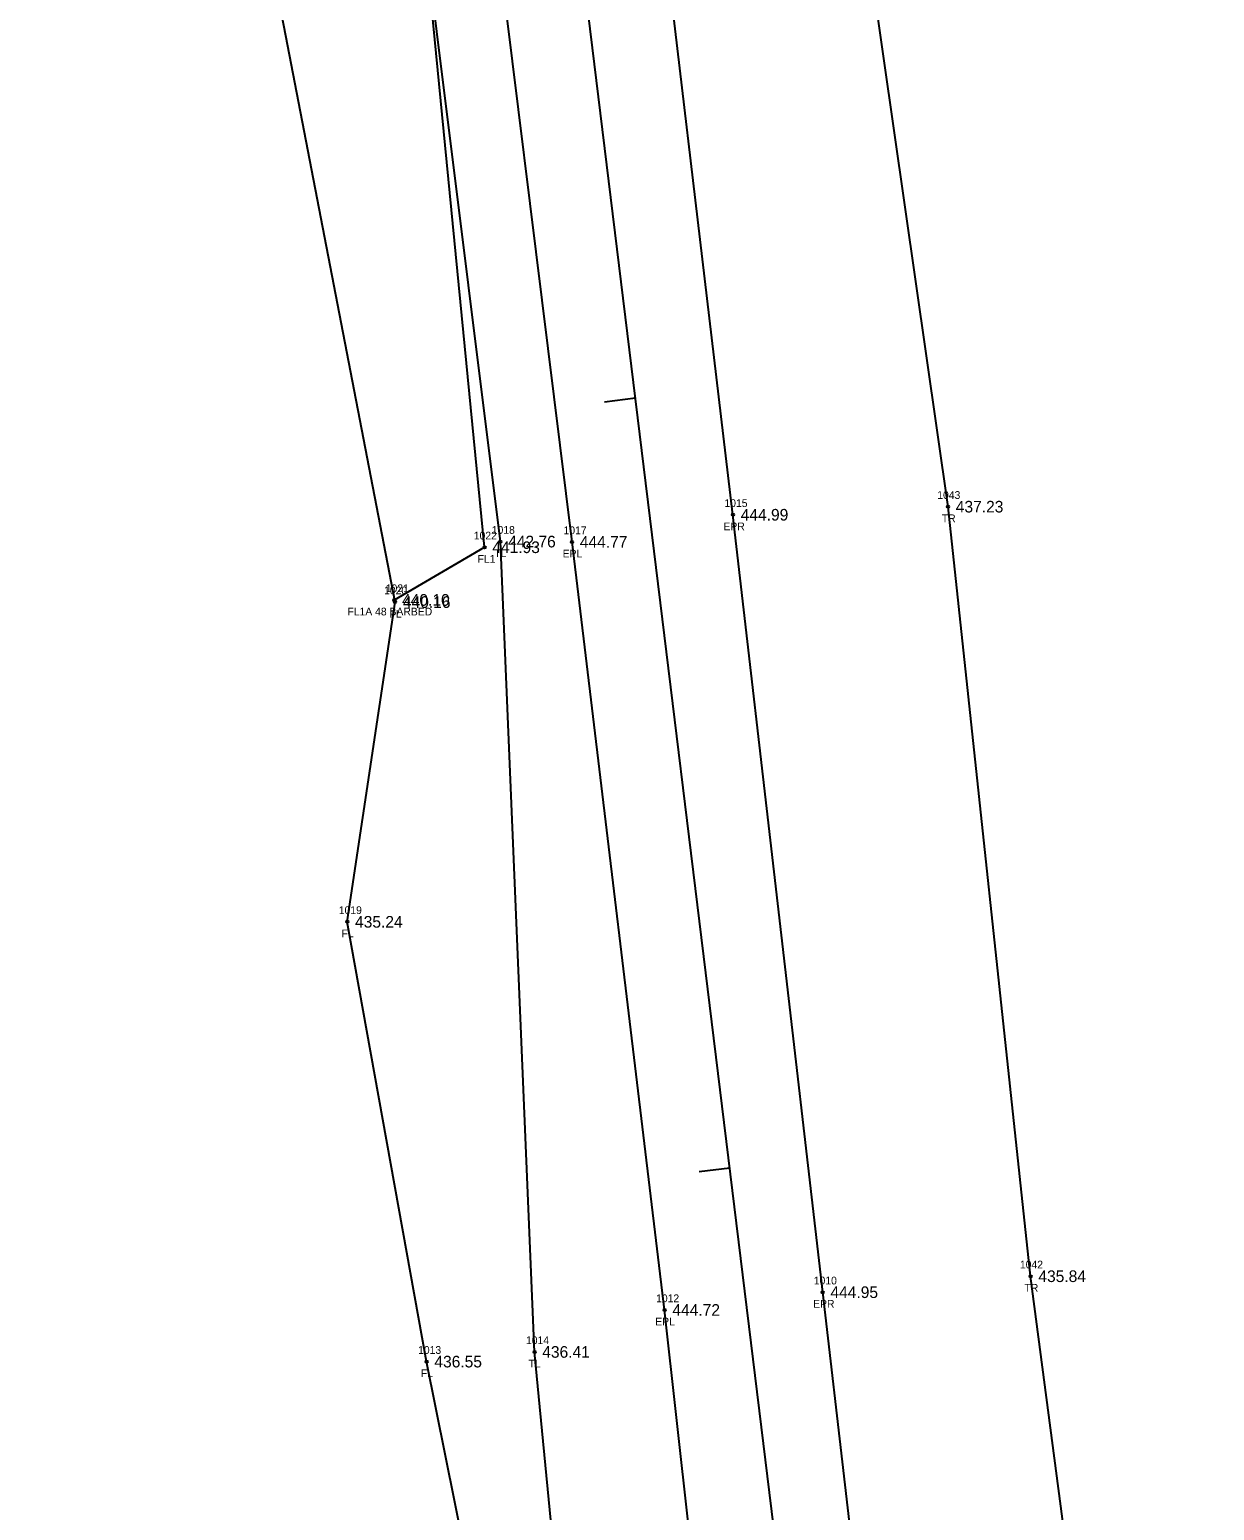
# Model space of a CAD drawing. Extents: x 1858454 to 1858924, y 1147053 to 1148170.
# Drawn here: x 1858633.8 to 1858786.6, y 1147243.8 to 1147434.7 of the extents above; entities that cross this region are included whole.
import ezdxf

# ---------------------------------------------------------------- set-up
doc = ezdxf.new("R2010")
doc.units = 0
for name, color, linetype in [('RD_EX_Fence_Other', 7, 'Continuous'), ('RD_EX_Fence_Other_txCode', 7, 'Continuous'), ('RD_EX_Road', 7, 'Continuous'), ('RD_EX_Road_txCode', 7, 'Continuous'), ('RD_EX_TX_Fence_Other_ELEV', 7, 'Continuous'), ('RD_EX_TX_Road_ELEV', 7, 'Continuous'), ('RD_EX_TX_VEG_ELEV', 7, 'Continuous'), ('RD_EX_VEG', 7, 'Continuous'), ('RD_EX_VEG_txCode', 7, 'Continuous'), ('RD_HC_Cl', 7, 'Continuous'), ('RD_HC_Data_Tic', 7, 'Continuous'), ('RD_SMD_Locator', 7, 'Continuous')]:
    doc.layers.add(name, color=color, linetype=linetype)

msp = doc.modelspace()

# ---------------------------------------------------------------- linework, layer by layer
at = {"layer": 'RD_EX_Fence_Other'}
for points in [[(1858680.85, 1147361.22), (1858692.48, 1147368.01), (1858682.77, 1147467.32), (1858662.27, 1147567.54), (1858637.61, 1147560.56)], [(1858724.59, 1147070.61), (1858704.63, 1147165.53), (1858685.01, 1147263.02), (1858674.78, 1147319.72), (1858680.95, 1147360.94), (1858660.16, 1147468.71), (1858637.61, 1147560.56)]]:
    msp.add_lwpolyline(points, dxfattribs=at)
at = {"layer": 'RD_EX_Road'}
for points in [[(1858739.58, 1147072.32), (1858726.74, 1147170.58), (1858715.7, 1147269.68), (1858703.76, 1147368.69), (1858691.45, 1147468.11), (1858680.5, 1147569.65), (1858689.32, 1147570.79)], [(1858760.33, 1147074.17), (1858747.61, 1147172.63), (1858736.08, 1147271.97), (1858724.51, 1147372.2), (1858712.86, 1147470.38), (1858700.06, 1147571.96), (1858689.32, 1147570.79)]]:
    msp.add_lwpolyline(points, dxfattribs=at)
at = {"layer": 'RD_EX_VEG'}
for points in [[(1858786.58, 1147073.62), (1858775.98, 1147174.64), (1858762.89, 1147274.03), (1858752.24, 1147373.24), (1858736.96, 1147479.89), (1858729.06, 1147571.9), (1858711.6, 1147670.3), (1858690.41, 1147764.38), (1858680.89, 1147862.43), (1858668.42, 1147961.01), (1858651.26, 1148061.01), (1858641.53, 1148160.37)], [(1858726.29, 1147071.02), (1858708.41, 1147166.41), (1858698.92, 1147264.27), (1858694.52, 1147368.74), (1858682.22, 1147467.57), (1858636.43, 1147636.58), (1858645.41, 1147757.54), (1858631.11, 1147856.08), (1858618.46, 1147956.68), (1858606.82, 1148055.62), (1858592.91, 1148154.69)]]:
    msp.add_lwpolyline(points, dxfattribs=at)
at = {"layer": 'RD_HC_Cl'}
msp.add_line((1858750.25, 1147074.55), (1858617.68, 1148156.23), dxfattribs=at)
at = {"layer": 'RD_HC_Data_Tic'}
for p, q in [((1858711.93, 1147387.21), (1858707.96, 1147386.73)), ((1858724.1, 1147287.96), (1858720.13, 1147287.47))]:
    msp.add_line(p, q, dxfattribs=at)
at = {"layer": 'RD_SMD_Locator'}
for centre in [(1858724.51, 1147372.2), (1858752.24, 1147373.24), (1858694.52, 1147368.74), (1858703.76, 1147368.69), (1858692.48, 1147368.01), (1858680.85, 1147361.22), (1858680.95, 1147360.94), (1858674.78, 1147319.72), (1858762.89, 1147274.03), (1858736.08, 1147271.97), (1858715.7, 1147269.68), (1858698.92, 1147264.27), (1858685.01, 1147263.02)]:
    msp.add_circle(centre, 0.15, dxfattribs=at)

# ---------------------------------------------------------------- texts
at = {"layer": 'RD_EX_Fence_Other_txCode'}
for s, p in [('1022', (1858691.09, 1147369.01)), ('FL1', (1858691.58, 1147366.01)), ('1020', (1858679.52, 1147361.94)), ('1021', (1858679.74, 1147362.22)), ('FL1A 48 BARBED', (1858674.8, 1147359.22)), ('FL', (1858680.22, 1147358.94)), ('1019', (1858673.68, 1147320.72)), ('FL', (1858674.05, 1147317.72)), ('1013', (1858683.91, 1147264.02)), ('FL', (1858684.28, 1147261.02))]:
    msp.add_text(s, height=1, dxfattribs=at).set_placement(p)
at = {"layer": 'RD_EX_Road_txCode'}
for s, p in [('1015', (1858723.41, 1147373.2)), ('1017', (1858702.66, 1147369.69)), ('EPR', (1858723.28, 1147370.2)), ('EPL', (1858702.55, 1147366.69)), ('1010', (1858734.93, 1147272.97)), ('1012', (1858714.6, 1147270.68)), ('EPR', (1858734.85, 1147269.97)), ('EPL', (1858714.49, 1147267.68))]:
    msp.add_text(s, height=1, dxfattribs=at).set_placement(p)
at = {"layer": 'RD_EX_TX_Fence_Other_ELEV'}
for s, p in [('441.93', (1858693.48, 1147367.26)), ('440.10', (1858681.85, 1147360.47)), ('440.16', (1858681.95, 1147360.19)), ('435.24', (1858675.78, 1147318.97)), ('436.55', (1858686.01, 1147262.27))]:
    msp.add_text(s, height=1.5, dxfattribs=at).set_placement(p)
at = {"layer": 'RD_EX_TX_Road_ELEV'}
for s, p in [('444.99', (1858725.51, 1147371.45)), ('444.77', (1858704.76, 1147367.94)), ('444.95', (1858737.08, 1147271.22)), ('444.72', (1858716.7, 1147268.93))]:
    msp.add_text(s, height=1.5, dxfattribs=at).set_placement(p)
at = {"layer": 'RD_EX_TX_VEG_ELEV'}
for s, p in [('437.23', (1858753.24, 1147372.49)), ('442.76', (1858695.52, 1147367.99)), ('435.84', (1858763.89, 1147273.28)), ('436.41', (1858699.92, 1147263.52))]:
    msp.add_text(s, height=1.5, dxfattribs=at).set_placement(p)
at = {"layer": 'RD_EX_VEG_txCode'}
for s, p in [('1043', (1858750.85, 1147374.24)), ('TR', (1858751.44, 1147371.24)), ('1018', (1858693.41, 1147369.74)), ('TL', (1858693.74, 1147366.74)), ('1042', (1858761.51, 1147275.03)), ('TR', (1858762.1, 1147272.03)), ('1014', (1858697.82, 1147265.27)), ('TL', (1858698.15, 1147262.27))]:
    msp.add_text(s, height=1, dxfattribs=at).set_placement(p)

doc.saveas('drawing.dxf')
